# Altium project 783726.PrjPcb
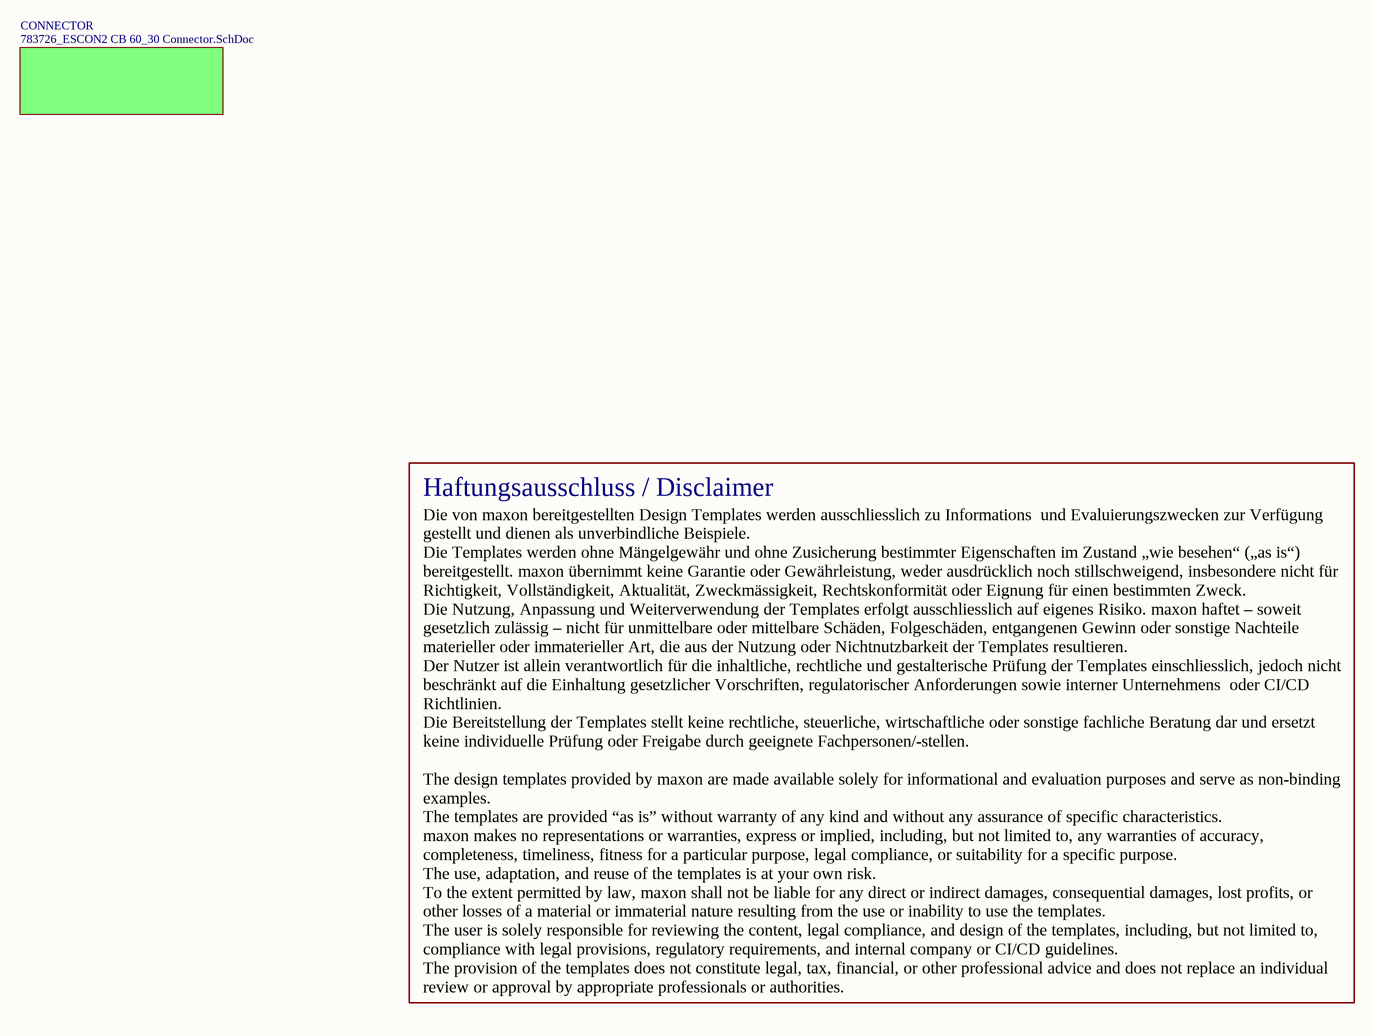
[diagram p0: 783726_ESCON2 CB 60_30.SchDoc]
CO_no: A100026771; Department: CCMC; PCB Eng Rev: 04; PCB unassembled: 783726
2 sheets, 145 parts. Net scope: global (net labels, ports and power ports of the same name join across sheets).
Board file: ESCON2 CB 60_30.PcbDoc
Sheets:
  783726_ESCON2 CB 60_30.SchDoc
    CONNECTOR = 783726_ESCON2 CB 60_30 Connector.SchDoc

## Sheet 783726_ESCON2 CB 60_30.SchDoc
size A3; SheetNumber: 1; SheetTotal: 2; Created: MMAGMHA; Modified: MMAGHIN; Reviewed: MMAGWAH; CreatedDate: 21.07.2022; ReviewedDate: 13.03.2024; ModifiedDate1: 12.03.2024

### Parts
*?  Disclaimer  (value not drawn)  (graphical)

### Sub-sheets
CONNECTOR = 783726_ESCON2 CB 60_30 Connector.SchDoc: no entries

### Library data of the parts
*? = CMP-002918-3: Disclaimer Text according to IFS-Doc:13538260

## Sheet 783726_ESCON2 CB 60_30 Connector.SchDoc
size A3; SheetNumber: 2; SheetTotal: 2; Created: MMAGMHA; Modified: MMAGHIN; Reviewed: MMAGWAH; CreatedDate: 21.07.2022; ReviewedDate: 13.03.2024; ModifiedDate1: 12.03.2024
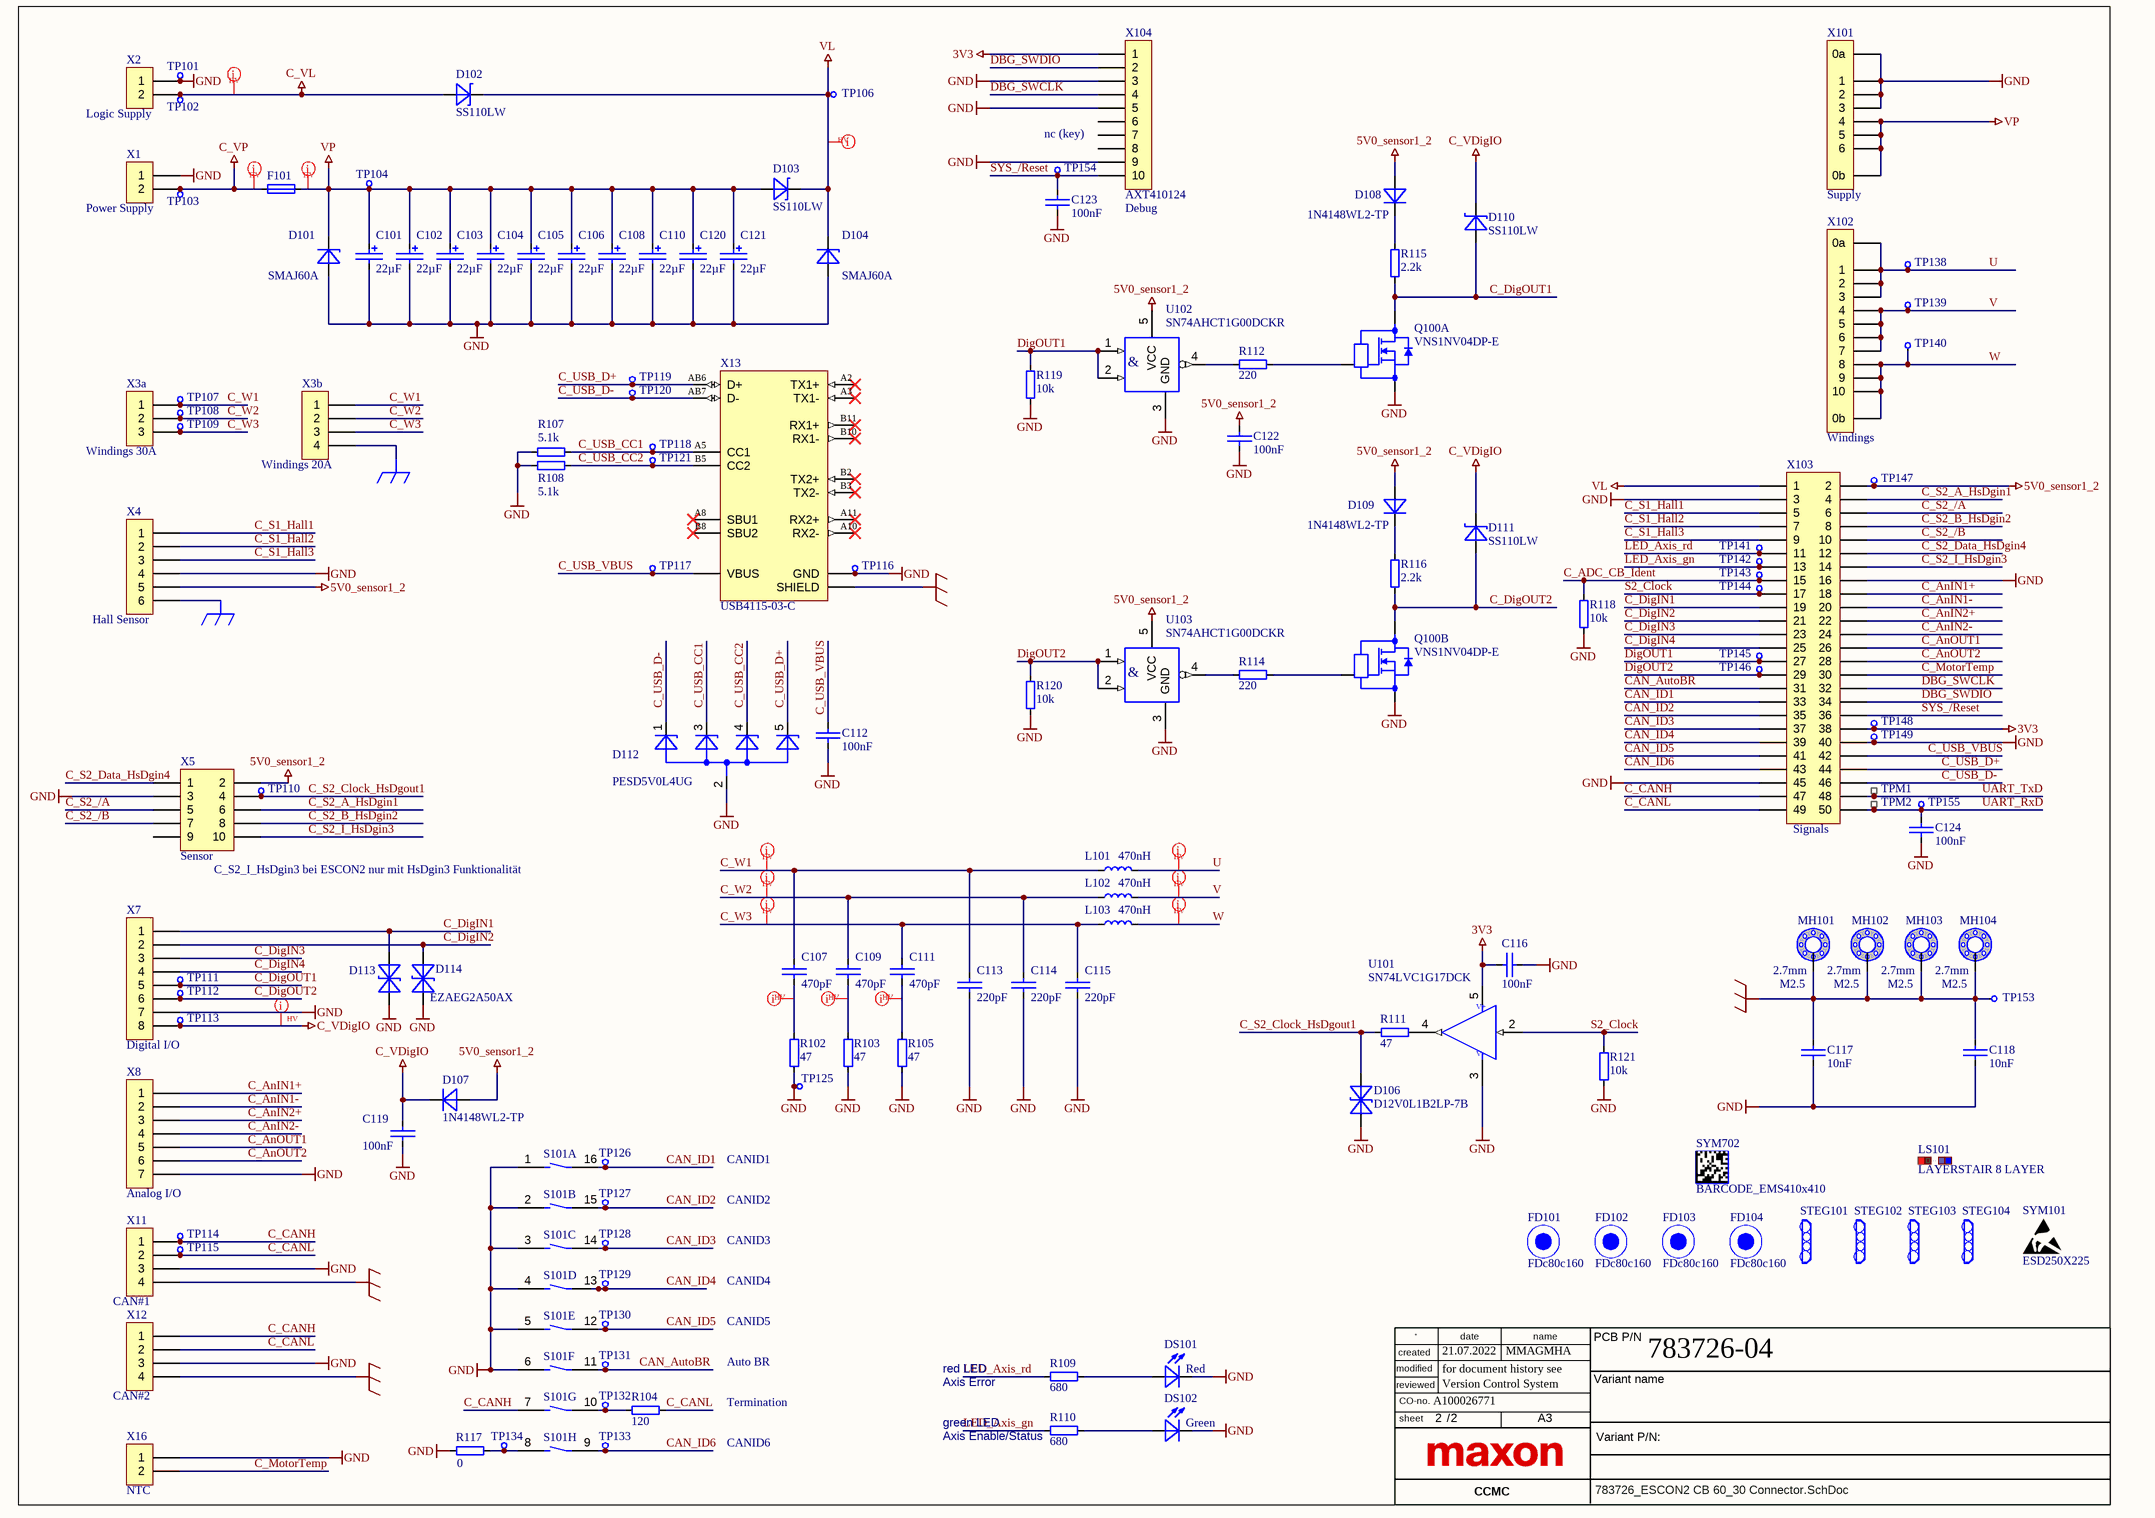
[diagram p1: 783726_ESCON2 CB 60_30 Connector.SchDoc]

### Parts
C101  value 22µF  [PANASONIC_F_VIB]  (hidden comment: EEHZA1K220P)
C102  value 22µF  [PANASONIC_F_VIB]  (hidden comment: EEHZA1K220P)
C103  value 22µF  [PANASONIC_F_VIB]  (hidden comment: EEHZA1K220P)
C104  value 22µF  [PANASONIC_F_VIB]  (hidden comment: EEHZA1K220P)
C105  value 22µF  [PANASONIC_F_VIB]  (hidden comment: EEHZA1K220P)
C106  value 22µF  [PANASONIC_F_VIB]  (hidden comment: EEHZA1K220P)
C107  value 470pF  [CAPC160X80X100L35N]  (hidden comment: 0603 470p)
C108  value 22µF  [PANASONIC_F_VIB]  (hidden comment: EEHZA1K220P)
C109  value 470pF  [CAPC160X80X100L35N]  (hidden comment: 0603 470p)
C110  value 22µF  [PANASONIC_F_VIB]  (hidden comment: EEHZA1K220P)
C111  value 470pF  [CAPC160X80X100L35N]  (hidden comment: 0603 470p)
C112  value 100nF  [CAPC100X50X70L25N]  (hidden comment: 0402 100nF)
C113  value 220pF  [CAPC160X80X100L35N]  (hidden comment: 0603 220pF)
C114  value 220pF  [CAPC160X80X100L35N]  (hidden comment: 0603 220pF)
C115  value 220pF  [CAPC160X80X100L35N]  (hidden comment: 0603 220pF)
C116  value 100nF  [CAPC100X50X70L25N]  (hidden comment: 0402 100nF)
C117  value 10nF  [CAPC200X125X150L47N]  (hidden comment: C0805C103KBRACAUTO)
C118  value 10nF  [CAPC200X125X150L47N]  (hidden comment: C0805C103KBRACAUTO)
C119  value 100nF  [CAPC160X80X100L35N]  (hidden comment: 0603 100nF)
C120  value 22µF  [PANASONIC_F_VIB]  (hidden comment: EEHZA1K220P)
C121  value 22µF  [PANASONIC_F_VIB]  (hidden comment: EEHZA1K220P)
C122  value 100nF  [CAPC100X50X70L25N]  (hidden comment: 0402 100nF)
C123  value 100nF  [CAPC100X50X70L25N]  (hidden comment: 0402 100nF)
C124  value 100nF  [CAPC100X50X70L25N]  (hidden comment: 0402 100nF)
D101  SMAJ60A  [DIOM519X260X262L114X145N]
D102  SS110LW  [SODFL359X170X143L65X95N]
D103  SS110LW  [SODFL359X170X143L65X95N]
D104  SMAJ60A  [DIOM519X260X262L114X145N]
D106  D12V0L1B2LP-7B  [DIONPDFN2_102X60X60L25X50N]
D107  1N4148WL2-TP  [DIODFN2_102X60X60L25X50N]
D108  1N4148WL2-TP  [DIODFN2_102X60X60L25X50N]
D109  1N4148WL2-TP  [DIODFN2_102X60X60L25X50N]
D110  SS110LW  [SODFL359X170X143L65X95N]
D111  SS110LW  [SODFL359X170X143L65X95N]
D112  PESD5V0L4UG  [SOT23-5P65_210X110L28X20N]
D113  EZAEG2A50AX  [DIONPC105X53X43L26N]  (value not drawn)
D114  EZAEG2A50AX  [DIONPC105X53X43L26N]
DS101  Color(s): Red  [LEDSC80X160X90L45N_RED]  (hidden comment: 598-8010-107F)
DS102  Color(s): Green  [LEDSC80X160X90L45N_GREEN]  (hidden comment: 598-8070-107F)
F101  0678H9400-02  [FUSC1008X305X305L170N]  (value not drawn)
FD101  FDc80c160  [FIDUCIAL_c80_c160]  (no BOM)
FD102  FDc80c160  [FIDUCIAL_c80_c160]  (no BOM)
FD103  FDc80c160  [FIDUCIAL_c80_c160]  (no BOM)
FD104  FDc80c160  [FIDUCIAL_c80_c160]  (no BOM)
L101  value 470nH  [INDM1335X1260X500L275X470N]  (hidden comment: SRP1245A-R47M)
L102  value 470nH  [INDM1335X1260X500L275X470N]  (hidden comment: SRP1245A-R47M)
L103  value 470nH  [INDM1335X1260X500L275X470N]  (hidden comment: SRP1245A-R47M)
LS101  LAYERSTAIR 8 LAYER  [8LS400X50w/oLETTERS_KEEPOUT]  (no BOM)
MH101  Diameter: 2.7mm  Metric screw: M2.5  [MTGNPH270A550V8H40]  (hidden comment: MTGNPH270A550V8H40)  (no BOM)
MH102  Diameter: 2.7mm  Metric screw: M2.5  [MTGNPH270A550V8H40]  (hidden comment: MTGNPH270A550V8H40)  (no BOM)
MH103  Diameter: 2.7mm  Metric screw: M2.5  [MTGNPH270A550V8H40]  (hidden comment: MTGNPH270A550V8H40)  (no BOM)
MH104  Diameter: 2.7mm  Metric screw: M2.5  [MTGNPH270A550V8H40]  (hidden comment: MTGNPH270A550V8H40)  (no BOM)
Q100  VNS1NV04DP-E  [SOIC8P127_490X599X175L83X41N]  (parts A,B of 2)
R102  value 47  [RESC320X160X90L47N]  (hidden comment: 1206 47R)
R103  value 47  [RESC320X160X90L47N]  (hidden comment: 1206 47R)
R104  value 120  [RESC200X125X84L35N]  (hidden comment: 0805 120R)
R105  value 47  [RESC320X160X90L47N]  (hidden comment: 1206 47R)
R107  value 5.1k  [RESC100X52X40L22N]  (hidden comment: 0402 5.1k)
R108  value 5.1k  [RESC100X52X40L22N]  (hidden comment: 0402 5.1k)
R109  value 680  [RESC100X52X40L22N]  (hidden comment: 0402 680R)
R110  value 680  [RESC100X52X40L22N]  (hidden comment: 0402 680R)
R111  value 47  [RESC100X52X40L22N]  (hidden comment: 0402 47R)
R112  value 220  [RESC100X52X40L22N]  (hidden comment: 0402 220R)
R114  value 220  [RESC100X52X40L22N]  (hidden comment: 0402 220R)
R115  value 2.2k  [RESC100X52X40L22N]  (hidden comment: 0402 2.2k)
R116  value 2.2k  [RESC100X52X40L22N]  (hidden comment: 0402 2.2k)
R117  value 0  [RESC100X52X40L22N]  (hidden comment: 0402 0)
R118  value 10k  [RESC100X52X40L22N]  (hidden comment: 0402 10k)
R119  value 10k  [RESC100X52X40L22N]  (hidden comment: 0402 10k)
R120  value 10k  [RESC100X52X40L22N]  (hidden comment: 0402 10k)
R121  value 10k  [RESC100X52X40L22N]  (hidden comment: 0402 10k)
S101  DHN-08F-T-V  [SOIC16P127_1139X671X151L61X41N]  (value not drawn)  (parts A,B,C,D,E,F,G,H of 8)
STEG101  Steg400X90_7Hole  [Steg_400X90_7Hole]  (value not drawn)  (no BOM)
STEG102  Steg400X90_7Hole  [Steg_400X90_7Hole]  (value not drawn)  (no BOM)
STEG103  Steg400X90_7Hole  [Steg_400X90_7Hole]  (value not drawn)  (no BOM)
STEG104  Steg400X90_7Hole  [Steg_400X90_7Hole]  (value not drawn)  (no BOM)
SYM101  ESD250X225  [ESD_copper_X-small]  (no BOM)
SYM702  BARCODE_EMS410x410  [BARCODE_EMS_410x410]  (no BOM)
TP101  TPc120  [TESTPOINT_c120]  (value not drawn)  (no BOM)
TP102  TPc120  [TESTPOINT_c120]  (value not drawn)  (no BOM)
TP103  TPc120  [TESTPOINT_c120]  (value not drawn)  (no BOM)
TP104  TPc120  [TESTPOINT_c120]  (value not drawn)  (no BOM)
TP106  TPc120  [TESTPOINT_c120]  (value not drawn)  (no BOM)
TP107  TPc120  [TESTPOINT_c120]  (value not drawn)  (no BOM)
TP108  TPc120  [TESTPOINT_c120]  (value not drawn)  (no BOM)
TP109  TPc120  [TESTPOINT_c120]  (value not drawn)  (no BOM)
TP110  TPc120  [TESTPOINT_c120]  (value not drawn)  (no BOM)
TP111  TPc120  [TESTPOINT_c120]  (value not drawn)  (no BOM)
TP112  TPc120  [TESTPOINT_c120]  (value not drawn)  (no BOM)
TP113  TPc120  [TESTPOINT_c120]  (value not drawn)  (no BOM)
TP114  TPc120  [TESTPOINT_c120]  (value not drawn)  (no BOM)
TP115  TPc120  [TESTPOINT_c120]  (value not drawn)  (no BOM)
TP116  TPc120  [TESTPOINT_c120]  (value not drawn)  (no BOM)
TP117  TPc120  [TESTPOINT_c120]  (value not drawn)  (no BOM)
TP118  TPc120  [TESTPOINT_c120]  (value not drawn)  (no BOM)
TP119  TPc120  [TESTPOINT_c120]  (value not drawn)  (no BOM)
TP120  TPc120  [TESTPOINT_c120]  (value not drawn)  (no BOM)
TP121  TPc120  [TESTPOINT_c120]  (value not drawn)  (no BOM)
TP125  TPc120  [TESTPOINT_c120]  (value not drawn)  (no BOM)
TP126  TPc120  [TESTPOINT_c120]  (value not drawn)  (no BOM)
TP127  TPc120  [TESTPOINT_c120]  (value not drawn)  (no BOM)
TP128  TPc120  [TESTPOINT_c120]  (value not drawn)  (no BOM)
TP129  TPc120  [TESTPOINT_c120]  (value not drawn)  (no BOM)
TP130  TPc120  [TESTPOINT_c120]  (value not drawn)  (no BOM)
TP131  TPc120  [TESTPOINT_c120]  (value not drawn)  (no BOM)
TP132  TPc120  [TESTPOINT_c120]  (value not drawn)  (no BOM)
TP133  TPc120  [TESTPOINT_c120]  (value not drawn)  (no BOM)
TP134  TPc120  [TESTPOINT_c120]  (value not drawn)  (no BOM)
TP138  TPc120  [TESTPOINT_c120]  (value not drawn)  (no BOM)
TP139  TPc120  [TESTPOINT_c120]  (value not drawn)  (no BOM)
TP140  TPc120  [TESTPOINT_c120]  (value not drawn)  (no BOM)
TP141  TPc120  [TESTPOINT_c120]  (value not drawn)  (no BOM)
TP142  TPc120  [TESTPOINT_c120]  (value not drawn)  (no BOM)
TP143  TPc120  [TESTPOINT_c120]  (value not drawn)  (no BOM)
TP144  TPc120  [TESTPOINT_c120]  (value not drawn)  (no BOM)
TP145  TPc120  [TESTPOINT_c120]  (value not drawn)  (no BOM)
TP146  TPc120  [TESTPOINT_c120]  (value not drawn)  (no BOM)
TP147  TPc120  [TESTPOINT_c120]  (value not drawn)  (no BOM)
TP148  TPc120  [TESTPOINT_c120]  (value not drawn)  (no BOM)
TP149  TPc120  [TESTPOINT_c120]  (value not drawn)  (no BOM)
TP153  TPc120  [TESTPOINT_c120]  (value not drawn)  (no BOM)
TP154  TPc120  [TESTPOINT_c120]  (value not drawn)  (no BOM)
TP155  TPc120  [TESTPOINT_c120]  (value not drawn)  (no BOM)
TPM1  TPMc50  [TESTPOINTMEASURE_c50]  (value not drawn)  (no BOM)
TPM2  TPMc50  [TESTPOINTMEASURE_c50]  (value not drawn)  (no BOM)
U101  SN74LVC1G17DCK  [SOT23-5P65_210X110L28X20N]
U102  SN74AHCT1G00DCKR  [SOT23-5P65_210X110L28X20N]
U103  SN74AHCT1G00DCKR  [SOT23-5P65_210X110L28X20N]
X1  428192214  [MOLEX_428192214]  (value not drawn)
X2  39281023  [MOLEX_39281023]  (value not drawn)
X3a  428193214  [MOLEX_428193214]  (value not drawn)
X3b  1720650204  [MOLEX_1720650204]  (value not drawn)
X4  430450612  [MOLEX_ 430450612]  (value not drawn)
X5  52601-S10-8LF  [AMPHENOL_52601-S10-8LF]  (value not drawn)
X7  5025840860  [MOLEX_5025840860]  (value not drawn)
X8  5025840760  [MOLEX_5025840760]  (value not drawn)
X11  5025840460  [MOLEX_5025840460]  (value not drawn)
X12  5025840460  [MOLEX_5025840460]  (value not drawn)
X13  USB4115-03-C  [GTC_USB4115-03-C]
X16  430450212  [MOLEX_ 430450212]  (value not drawn)
X101  UMPT-06-07.5-L-V-S-W  [SAMTEC_UMPT-06-07.5-L-V-S-W]  (value not drawn)
X102  UMPT-10-07.5-L-V-S-W  [SAMTEC_UMPT-10-07.5-L-V-S-W]  (value not drawn)
X103  ERM8-025-08.0-L-DV  [SAMTEC_ERM8-025-08.0-L-DV]  (value not drawn)
X104  AXT410124  [PANASONIC_AXT410124]

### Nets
3V3: C116.2 TP148.1 U101.5(VCC) X103.38 X104.1
5V0_sensor1_2: C122.2 D107.2(A) D108.2(A) D109.2(A) TP147.1 U102.5(VCC) U103.5(VCC) X4.5 X5.2 X103.2
C_VDigIO: C119.2 D107.1(C) D110.1(C) D111.1(C) TP113.1 X7.8
C_VL: D102.2(A) TP102.1 X2.2
C_VP: F101.1 TP103.1 X1.2
GND: C101.2(-) C102.2(-) C103.2(-) C104.2(-) C105.2(-) C106.2(-) C108.2(-) C110.2(-) C112.1 C113.1 C114.1 C115.1 C116.1 C117.1 C118.1 C119.1 C120.2(-) C121.2(-) C122.1 C123.1 C124.1 D101.2(A) D104.2(A) D106.1 D112.2(A) D113.1 D114.1 DS101.1(C) DS102.1(C) Q100.1(S1) Q100.3(S2) R102.1 R103.1 R105.1 R107.2 R108.2 R117.1 R118.1 R119.1 R120.1 R121.1 S101.1 S101.2 S101.3 S101.4 S101.5 S101.6 TP101.1 TP116.1 TP125.1 TP149.1 U101.3(GND) U102.3(GND) U103.3(GND) X1.1 X2.1 X4.4 X5.3 X7.7 X8.7 X11.3 X12.3 X13.AB112(GND) X16.1 X101.0a X101.1 X101.2 X101.3 X103.3 X103.16 X103.40 X103.45 X104.3 X104.5 X104.9
SGND: C117.2 C118.2 MH101.1 MH102.1 MH103.1 MH104.1 TP153.1 X3b.4 X4.6 X11.4 X12.4 X13.SHIELD
VL: D102.1(C) D103.1(C) D104.1(C) TP106.1 X103.1
VP: C101.1(+) C102.1(+) C103.1(+) C104.1(+) C105.1(+) C106.1(+) C108.1(+) C110.1(+) C120.1(+) C121.1(+) D101.1(C) D103.2(A) F101.2 TP104.1 X101.0b X101.4 X101.5 X101.6
C_ADC_CB_Ident: R118.2 TP143.1 X103.15
C_AnIN1+: X8.1 X103.18
C_AnIN1-: X8.2 X103.20
C_AnIN2+: X8.3 X103.22
C_AnIN2-: X8.4 X103.24
C_AnOUT1: X8.5 X103.26
C_AnOUT2: X8.6 X103.28
C_CANH: S101.7 TP114.1 X11.1 X12.1 X103.47
C_CANL: R104.2 TP115.1 X11.2 X12.2 X103.49
C_DigIN1: D113.2 X7.1 X103.19
C_DigIN2: D114.2 X7.2 X103.21
C_DigIN3: X7.3 X103.23
C_DigIN4: X7.4 X103.25
C_DigOUT1: D110.2(A) Q100.6(D1) R115.1 TP111.1 X7.5
C_DigOUT2: D111.2(A) Q100.5(D2) R116.1 TP112.1 X7.6
C_MotorTemp: X16.2 X103.30
C_S1_Hall1: X4.1 X103.5
C_S1_Hall2: X4.2 X103.7
C_S1_Hall3: X4.3 X103.9
C_S2_/A: X5.5 X103.6
C_S2_/B: X5.7 X103.10
C_S2_A_HsDgin1: X5.6 X103.4
C_S2_B_HsDgin2: X5.8 X103.8
C_S2_Clock_HsDgout1: D106.2 R111.1 TP110.1 X5.4
C_S2_Data_HsDgin4: X5.1 X103.12
C_S2_I_HsDgin3: X5.10 X103.14
C_USB_CC1: D112.3 R107.1 TP118.1 X13.A5(CC1)
C_USB_CC2: D112.4 R108.1 TP121.1 X13.B5(CC2)
C_USB_D+: D112.5 TP119.1 X13.AB6(D+) X103.44
C_USB_D-: D112.1 TP120.1 X13.AB7(D-) X103.46
C_USB_VBUS: C112.2 TP117.1 X13.AB49(VBUS) X103.42
C_W1: C107.2 C113.2 L101.1 TP107.1 X3a.1 X3b.1
C_W2: C109.2 C114.2 L102.1 TP108.1 X3a.2 X3b.2
C_W3: C111.2 C115.2 L103.1 TP109.1 X3a.3 X3b.3
CAN_AutoBR: S101.11 TP131.1 X103.31
CAN_ID1: S101.16 TP126.1 X103.33
CAN_ID2: S101.15 TP127.1 X103.35
CAN_ID3: S101.14 TP128.1 X103.37
CAN_ID4: S101.13 TP129.1 X103.39
CAN_ID5: S101.12 TP130.1 X103.41
CAN_ID6: S101.9 TP133.1 X103.43
DBG_SWCLK: X103.32 X104.4
DBG_SWDIO: X103.34 X104.2
DigOUT1: R119.2 TP145.1 U102.1(inA) U102.2(inB) X103.27
DigOUT2: R120.2 TP146.1 U103.1(inA) U103.2(inB) X103.29
LED_Axis_gn: R110.1 TP142.1 X103.13
LED_Axis_rd: R109.1 TP141.1 X103.11
S2_Clock: R121.2 TP144.1 U101.2(inA) X103.17
SYS_/Reset: C123.2 TP154.1 X103.36 X104.10
U: L101.2 TP138.1 X102.0a X102.1 X102.2 X102.3
UART_RxD: C124.2 TP155.1 TPM2.1 X103.50
UART_TxD: TPM1.1 X103.48
V: L102.2 TP139.1 X102.4 X102.5 X102.6 X102.7
W: L103.2 TP140.1 X102.0b X102.8 X102.9 X102.10
NetC107_1: C107.1 R102.2
NetC109_1: C109.1 R103.2
NetC111_1: C111.1 R105.2
NetD108_1: D108.1(C) R115.2
NetD109_1: D109.1(C) R116.2
NetDS101_2: DS101.2(A) R109.2
NetDS102_2: DS102.2(A) R110.2
NetQ100_2: Q100.2(IN1) R112.2
NetQ100_4: Q100.4(IN2) R114.2
NetR104_1: R104.1 S101.10 TP132.1
NetR111_2: R111.2 U101.4(outY)
NetR112_1: R112.1 U102.4(outY)
NetR114_1: R114.1 U103.4(outY)
NetR117_2: R117.2 S101.8 TP134.1

Not connected (* = marked no-connect by the designer): X5 9; X13 A2(TX1+)* A3(TX1-)* A8(SBU1)* A10(RX2-)* A11(RX2+)* B2(TX2+)* B3(TX2-)* B8(SBU2)* B10(RX1-)* B11(RX1+)*; X104 6 7 8

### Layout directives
net class HV: C_VDigIO, C_VL, C_VP, C_W1, C_W2, C_W3, NetC107_1, NetC109_1, NetC111_1, U, V, VL, VP, W

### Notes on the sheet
- Logic Supply
- nc (key)
- Power Supply
- (near X104) Debug
- (near X101) Supply
- (near X3a) Windings 30A
- (near X102) Windings
- (near X3b) Windings 20A
- (near X4) Hall Sensor
- (near X5) Sensor
- (near X103) Signals
- (near X5) C_S2_I_HsDgin3 bei ESCON2 nur mit HsDgin3 Funktionalität
- Digital I/O
- CANID1
- (near X8) Analog I/O
- CANID2
- CANID3
- CAN#1
- CANID4
- CANID5
- (near X12) CAN#2
- Auto BR
- red LED
- Axis Error
- CANID6
- Termination
- green LED
- Axis Enable/Status
- (near X16) NTC

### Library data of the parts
C101-C106 C108 C110 C120 C121 = CMP-000967-5: Polymer Hybrid Elco 22uF >=80V 20% D=8mm, H=10.5mm; Manufacturer: Panasonic; Vibration proof: N; Ripple Current: 1.55A; Endurance: >=10'000h @105°C; Maximum Working Voltage: 80V; Case (Metric): G, D=8mm, H=10.5mm
C107 C109 C111 = CMP-001011-3: 470p C0G/NP0/X7R >=100V 20%; Manufacturer: X; Part Number: Ceramic, 0603, 470pF, 20%, >=100V, C0G/NP0/X7R, @, Soft Termination: N, -55°C to 125°C; Maximum Working Voltage: 100V; Case (Metric): 1608; Soft Termination: N
C112 = CMP-001306-1: 100nF X7R >=50V 20%; Part Number: Ceramic, 0402, 100nF, 20%, >=50V, X7R, @, Soft Termination: N, -55°C to 125°C; Manufacturer: X; Soft Termination: N; Case (Metric): 1005; Maximum Working Voltage: 50V
C113-C115 = CMP-001012-4: 220pF C0G/NP0/X7R >=100V 20%; Manufacturer: X; Part Number: Ceramic, 0603, 220pF, 20%, >=100V, C0G/NP0/X7R, @, Soft Termination: N, -55°C to 125°C; Case (Metric): 1608; Maximum Working Voltage: 100V; Soft Termination: N
C116 C122-C124 = CMP-000709-3: 100nF X7R >=16V 20%; Part Number: Ceramic, 0402, 100nF, 20%, >=16V, X7R, @, Soft Termination: N, -55°C to 125°C; Manufacturer: X; Maximum Working Voltage: 16V; Soft Termination: N; Case (Metric): 1005
C117 C118 = CMP-000937-4: 10nF X7R >=630V 20%; Manufacturer: Murata; Dielectric Withstanding Voltage: > 850V 1sec; Case (Metric): 2012; Soft Termination: N; Maximum Working Voltage: 630V
C119 = CMP-000703-3: 100nF X7R >=100V 20%; Part Number: Ceramic, 0603, 100nF, 20%, >=100V, X7R, @, Soft Termination: N, -55°C to 125°C; Manufacturer: X; Soft Termination: N; Case (Metric): 1608; Maximum Working Voltage: 100V
D101 D104 = CMP-001103-4: Transient Voltage Suppressor Diode, 60V V(RWM), Unidirectional, 400W, 1 Element, DO-214AC; Manufacturer: X; Element Configuration: Single; Clamping Voltage: 96.8V; Breakdown Voltage: 66.7V; Polarity: Unipolar
D102 D103 D110 D111 = CMP-000633-9: Schottky Diode, >=90V, >=1A, SOD-123FL/SOD-123W; Manufacturer: Taiwan Semiconductor; RMS Current: 1A; Polarity: Unipolar; Reverse Voltage: 90V; Element Configuration: Single
D106 = CMP-001106-5: Transient Voltage Suppressor Diode, 12V V(RWM), Bidirectional, 100W, 1 Element, SOD-882/DFN1006; Manufacturer: Diodes; Element Configuration: Single; Breakdown Voltage: 13V; Polarity: Bipolar
D107-D109 = CMP-000606-13: Diode Switching, >=70V, >=150mA, SOD882/DFN1006/0402/SOD-923F; Manufacturer: MCC; Polarity: Unipolar; Recovery time: 4ns; Reverse Voltage: 70V; Element Configuration: Single; RMS Current: 150mA
D112 = CMP-000635-10: Transient Voltage Suppressor Diode, 4-Line, 5V V(RWM), Unidirectional, 30W, 4 Element , SOT353/SC-88A; Manufacturer: Nexperia; Min Breakdown Voltage: 6.46V; Nummber of Pins: 5; Element Configuration: Array; Common Anode; Max Junction Temperature: 150°C; Polarity: Unipolar; Breakdown Voltage: 6.8V; Nummber of Elements: 4; Max Breakdown Voltage: 7.14V; Clamping Voltage: 12V
D113 D114 = CMP-000066-17: Transient Voltage Suppressor Diode, 30V V(RWM), Bidirectional, ESD, 1 Element, 0402; Manufacturer: Panasonic; Element Configuration: Single; Polarity: Bipolar
DS101 = CMP-000723-6: Single Color Chip LED, red, 0603; Manufacturer: Dialight; Luminous Intensity: >5mcd@20mA; Wavelength: 617-640nm
DS102 = CMP-000722-5: Single Color Chip LED, green, 0603; Manufacturer: Dialight; Luminous Intensity: >5mcd@20mA; Wavelength: 564...575nm
F101 = CMP-001105-4: Electric Fuse, Fast Acting, 40A, 72VDC, Surface Mount; Manufacturer: BelFuse; Maximum Working Voltage: 72V; Melting Integral: 400
FD101-FD104 = CMP-000010-5: Fiducial, Global, Round; 0.80 mm D, 1.60 mm Clearance
L101-L103 = CMP-001104-3: Inductor Shielded, 0.47uH, 20%, I_RMS>34A, I_Sat>58A, R<1.3mOhm, 13.0x14.0mm, Height<=5mm; RMS Current: 34A; Polarity: N; Saturation Current: 58A; DC Resistance: 1.3m
LS101 = CMP-001088-3: Layer Stair 8 Layer
MH101-MH104 = CMP-000029-10: Mounting Hole, Non-Plated; 5.50 mm Clearance, 2.70 mm Hole (with 8 vias); pin to pad: 1>2+3+4+5+6+7+8+9
Q100 = CMP-001108-5: N-Channel MOSFET, Self Protected, 36V, 0.5ohm, SO-8; pin to pad: 5>5+6 6>7+8; Manufacturer: ST Microelectronics; Element Configuration: N-CH, Self Protected
R102 R103 R105 = CMP-000398-10: 47R 1% 250mW 100ppm; Part Number: Thick-Film, 1206, 47, 1%, 250mW@70°C, 200V, 100ppm, -55°C to 155°C; Manufacturer: X; Max Junction Temperature: 155°C; AECQ: N; Case (Metric): 3216; Power Rating Temperature: 70°C; Maximum Working Voltage: 200V; Maximum Overload Voltage: 400V
R104 = CMP-000325-10: 120R 1% 125mW 100ppm; Part Number: Thick-Film, 0805, 120, 1%, 125mW@70°C, 150V, 100ppm, -55°C to 155°C; Manufacturer: X; Max Junction Temperature: 155°C; AECQ: N; Case (Metric): 2012; Power Rating Temperature: 70°C; Maximum Working Voltage: 150V; Maximum Overload Voltage: 300V
R107 R108 = CMP-000206-11: 5.1k 1% 62.5mW 100ppm; Part Number: Thick-Film, 0402, 5.1k, 1%, 62.5mW@70°C, 50V, 100ppm, -55°C to 155°C; Manufacturer: X; Max Junction Temperature: 155°C; AECQ: N; Case (Metric): 1050; Power Rating Temperature: 70°C; Maximum Working Voltage: 50V; Maximum Overload Voltage: 100V
R109 R110 = CMP-000185-11: 680R 1% 62.5mW 100ppm; Part Number: Thick-Film, 0402, 680, 1%, 62.5mW@70°C, 50V, 100ppm, -55°C to 155°C; Manufacturer: X; Max Junction Temperature: 155°C; AECQ: N; Case (Metric): 1050; Power Rating Temperature: 70°C; Maximum Working Voltage: 50V; Maximum Overload Voltage: 100V
R111 = CMP-000161-11: 47R 1% 62.5mW 100ppm; Part Number: Thick-Film, 0402, 47, 1%, 62.5mW@70°C, 50V, 100ppm, -55°C to 155°C; Manufacturer: X; Max Junction Temperature: 155°C; AECQ: N; Case (Metric): 1050; Power Rating Temperature: 70°C; Maximum Working Voltage: 50V; Maximum Overload Voltage: 100V
R112 R114 = CMP-000173-11: 220R 1% 62.5mW 100ppm; Part Number: Thick-Film, 0402, 220, 1%, 62.5mW@70°C, 50V, 100ppm, -55°C to 155°C; Manufacturer: X; Max Junction Temperature: 155°C; AECQ: N; Case (Metric): 1050; Power Rating Temperature: 70°C; Maximum Working Voltage: 50V; Maximum Overload Voltage: 100V
R115 R116 = CMP-000197-11: 2.2k 1% 62.5mW 100ppm; Part Number: Thick-Film, 0402, 2.2k, 1%, 62.5mW@70°C, 50V, 100ppm, -55°C to 155°C; Manufacturer: X; Max Junction Temperature: 155°C; AECQ: N; Case (Metric): 1050; Power Rating Temperature: 70°C; Maximum Working Voltage: 50V; Maximum Overload Voltage: 100V
R117 = CMP-000466-10: 0R Jumper; Part Number: Thick-Film, 0402, 0, -55°C to 155°C; Manufacturer: X; Case (Metric): 1050; RMS Current: 1A; Maximum Overload Voltage: 100V; Max Junction Temperature: 155°C; Maximum Working Voltage: 50V
R118-R121 = CMP-000492-11: 10k 1% 62.5mW 100ppm; Part Number: Thick-Film, 0402, 10k, 1%, 62.5mW@70°C, 50V, 100ppm, -55°C to 155°C; Manufacturer: X; Max Junction Temperature: 155°C; AECQ: N; Case (Metric): 1050; Power Rating Temperature: 70°C; Maximum Working Voltage: 50V; Maximum Overload Voltage: 100V
S101 = CMP-001031-3: Slide Dip Switch, 8 Switches, 0.025A, 24VDC, SMD; Manufacturer: Diptronics
STEG101-STEG104 = CMP-000007-5: Breakaway tabs; 4.00 mm L X 0.90 mm W, 7 Hole
SYM101 = CMP-000019-5: ESD-Sign; 2.5 mm L X 2.25 mm W
SYM702 = CMP-001187-11: Barcode EMS; 4.1 x 4.1 mm
TP101-TP104 TP106-TP121 TP125-TP134 TP138-TP149 TP153-TP155 = CMP-000014-7: Test Point; 1 pin, 1.20 mm D
TPM1 TPM2 = CMP-001150-4: Test point measure; 1 pin, 0.50 mm D
U101 = CMP-001041-6: Single buffer with Schmitt-Trigger inputs; Manufacturer: Texas Instruments; AECQ: N; Max Supply Voltage: 5.5V; Min Supply Voltage: 1.65V
U102 U103 = CMP-002037-1: Single, 2-Input NAND Gate, 5V; Min Supply Voltage: 4.5V; Max Supply Voltage: 5.5V
X1 = CMP-001093-5: 10.00mm Pitch Mini-Fit Sr. Header, Single Row, Vertical, 1.57mm PCB Thickness, 2 Circuits; Manufacturer: Molex; Number of Contacts: 2; Operating Current: 50A; Operating Voltage: 600V
X2 = CMP-001018-5: Mini-Fit Jr. Vertical Header, 4.20mm Pitch, Dual Row, 2 Circuits, without Snap-in Plastic Peg PCB Lock, Tin, Natural; Manufacturer: Molex; Number of Contacts: 2; Operating Voltage: 600V; Operating Current: 9A
X3a = CMP-001094-4: 10.00mm Pitch Mini-Fit Sr. Header, Single Row, Vertical, 1.57mm PCB Thickness, 3 Circuits; Manufacturer: Molex; Number of Contacts: 3; Operating Current: 50A; Operating Voltage: 600V
X3b = CMP-001095-4: Mega-Fit Slim Vertical Header, Through Hole, 5.70mm Pitch, Dual Row, 4 Circuits, Black; Manufacturer: Molex; Number of Contacts: 4; Operating Current: 23.5A; Operating Voltage: 600V
X4 = CMP-001098-6: Micro-Fit 3.0 Vertical Header, 3.00mm Pitch, Dual Row, 6 Circuits, with PCB Polarizing Peg, Black; Manufacturer: Molex; Operating Voltage: 600V; Number of Contacts: 6; Operating Current: 8.5A
X5 = CMP-001165-3: Header, 2.54mm Pitch, Dual Row, SMT, Vertical, 10 Circuits; Manufacturer: Amphenol; Operating Voltage: 500V; Number of Contacts: 10; Operating Current: 3A
X7 = CMP-001014-7: 1.50mm Pitch, CLIK-Mate PCB Receptacle, Single Row, Surface Mount, Tin Plating, Positive Lock, with Pick-and-Place Polyimide Tape, 8 Circuits, Beige; Manufacturer: Molex; Number of Contacts: 8; Operating Current: 2A; Operating Voltage: 100V
X8 = CMP-001015-7: 1.50mm Pitch, CLIK-Mate PCB Receptacle, Single Row, Surface Mount, Tin Plating, Positive Lock, with Pick-and-Place Polyimide Tape, 7 Circuits, Beige; Manufacturer: Molex; Operating Voltage: 100V; Operating Current: 2A; Number of Contacts: 7
X11 X12 = CMP-001170-6: 1.50mm Pitch, CLIK-Mate PCB Receptacle, Single Row, Surface Mount, Tin Plating, Positive Lock, with Pick-and-Place Polyimide Tape, 4 Circuits, Beige; Manufacturer: Molex; Number of Contacts: 4; Operating Voltage: 100V; Operating Current: 2A
X13 = CMP-001110-9: USB Type C, SHLD, 24poles, vertical; pin to pad: AB6>A6+B6 AB7>A7+B7 AB49>A4+A9+B4+B9 AB112>B1+A12+B12+A1 SHIELD>S1+S2+S3+S4; Manufacturer: GTC
X16 = CMP-001107-4: Micro-Fit 3.0 Vertical Header, 3.00mm Pitch, Dual Row, 2 Circuits, with PCB Polarizing Peg, Black; Manufacturer: Molex; Operating Voltage: 600V; Number of Contacts: 2; Operating Current: 8.5A
X101 = CMP-001100-9: 2.00 mm mPOWER® Ultramikro-Power-Socket, 6-polig; Manufacturer: Samtec; Number of Contacts: 6; Operating Current: 18A; Operating Voltage: 460V
X102 = CMP-001189-6: 2.00 mm mPOWER® Ultramikro-Power-Socket, 10-polig; Manufacturer: Samtec; Number of Contacts: 10; Operating Current: 18A; Operating Voltage: 460V
X103 = CMP-001102-8: 0.80 mm Edge Rate® Rugged High Speed Terminal; Number of Contacts: 50; Operating Current: 1.4A; Operating Voltage: 225V; System: Connector
X104 = CMP-001083-11: Board to Board Connector, 2*5 pole, SMD, 0.4mm pitch, 1.5mm stacking Height; Manufacturer: Panasonic; Number of Contacts: 10; Operating Current: 300mA; Operating Voltage: 60V

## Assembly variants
783727: not fitted D113 D114 R117 X104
